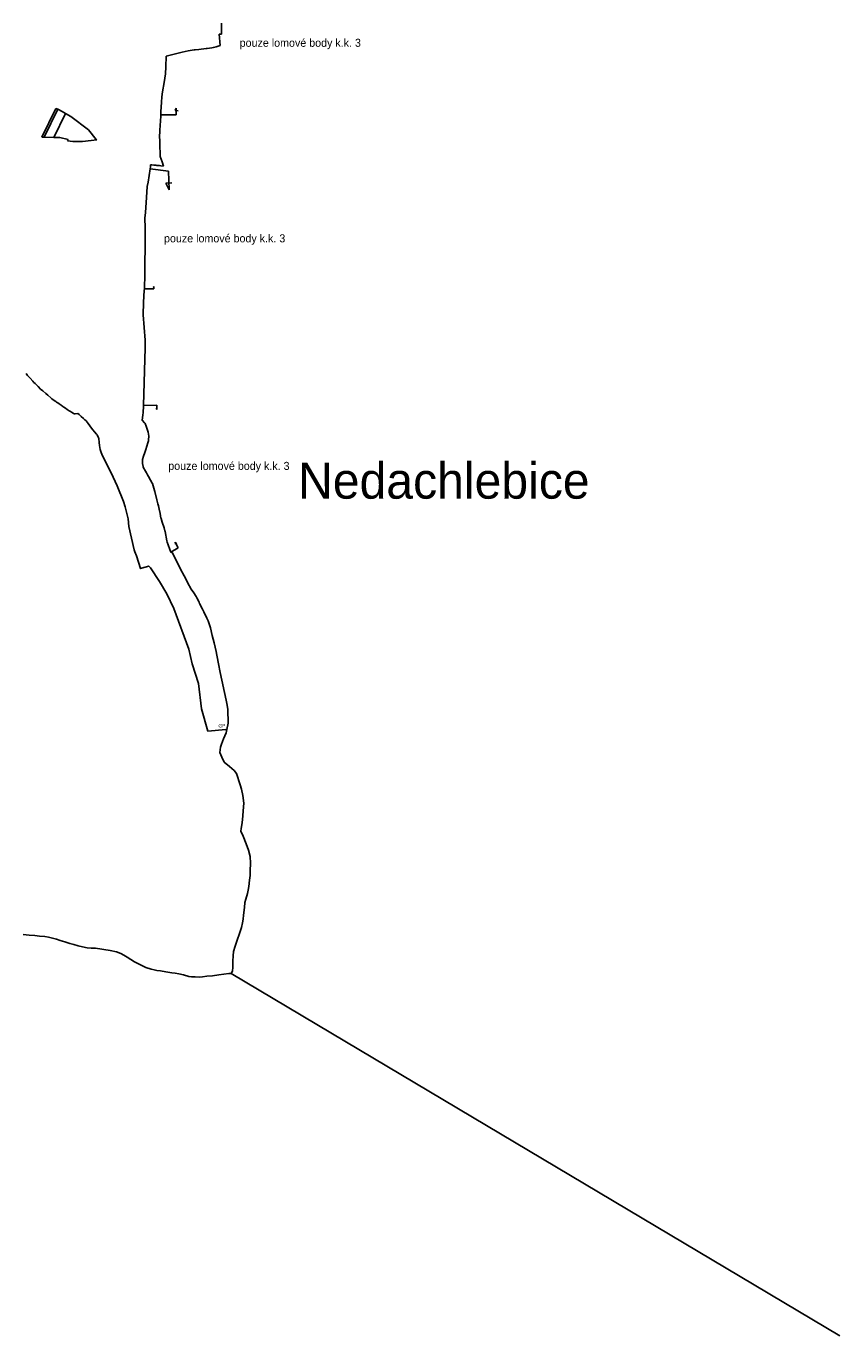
# Model space of a CAD drawing. Extents: x -534397 to -527742, y -1181460 to -1175250.
# Drawn here: x -530094 to -528058, y -1181460 to -1178187 of the extents above; entities that cross this region are included whole.
import ezdxf

# ---------------------------------------------------------------- set-up
doc = ezdxf.new("R2010")
doc.units = 0
for name, color, linetype in [('Hranice krajů', 7, 'Continuous'), ('Hranice obcí', 7, 'Continuous'), ('Hranice parcel', 7, 'Continuous'), ('Hranice státní', 7, 'Continuous')]:
    doc.layers.add(name, color=color, linetype=linetype)

msp = doc.modelspace()

# ---------------------------------------------------------------- linework, layer by layer
at = {"layer": 'Hranice obcí'}
for p, q in [((-530054.2, -1178464.1), (-530019.1, -1178392.1)), ((-530014.6, -1178394.3), (-530048.8, -1178464.3)), ((-530019.1, -1178392.1), (-530014.6, -1178394.3)), ((-530003.5, -1178399.7), (-530014.6, -1178394.3)), ((-530024.3, -1178465.1), (-529994.9, -1178404.8)), ((-529994.9, -1178404.8), (-530003.5, -1178399.7)), ((-529994.9, -1178404.8), (-529982.1, -1178412.4)), ((-529982.1, -1178412.4), (-529938.1, -1178445.4)), ((-529938.1, -1178445.4), (-529918.8, -1178469.8)), ((-530048.8, -1178464.3), (-530054.2, -1178464.1)), ((-530048.8, -1178464.3), (-530024.3, -1178465.1)), ((-530009.5, -1178464.6), (-530024.3, -1178465.1)), ((-529988.6, -1178469.9), (-530009.5, -1178464.6)), ((-529990.1, -1178473), (-529988.6, -1178469.9)), ((-529977.2, -1178475.2), (-529990.1, -1178473)), ((-529952.9, -1178475), (-529977.2, -1178475.2)), ((-529930.9, -1178472), (-529952.9, -1178475)), ((-529916.5, -1178470.8), (-529930.9, -1178472)), ((-529918.8, -1178469.8), (-529916.5, -1178470.8))]:
    msp.add_line(p, q, dxfattribs=at)
at = {"layer": 'Hranice parcel'}
for p, q in [((-529605, -1178178.9), (-529604.9, -1178206.2)), ((-529604.9, -1178206.2), (-529610.7, -1178206.2)), ((-529610.7, -1178206.2), (-529608.1, -1178234.8)), ((-529743.3, -1178261.9), (-529744.2, -1178287.8)), ((-529723.2, -1178256.8), (-529743.3, -1178261.9)), ((-529703.7, -1178251.8), (-529723.2, -1178256.8)), ((-529688.2, -1178247.9), (-529703.7, -1178251.8)), ((-529683.1, -1178247.2), (-529688.2, -1178247.9)), ((-529673.1, -1178245.9), (-529683.1, -1178247.2)), ((-529670.6, -1178245.6), (-529673.1, -1178245.9)), ((-529661.8, -1178244.7), (-529670.6, -1178245.6)), ((-529643.5, -1178242.7), (-529661.8, -1178244.7)), ((-529640.6, -1178242.4), (-529643.5, -1178242.7)), ((-529629, -1178240.6), (-529640.6, -1178242.4)), ((-529626.1, -1178239.9), (-529629, -1178240.6)), ((-529624.8, -1178239.6), (-529626.1, -1178239.9)), ((-529618.8, -1178238), (-529624.8, -1178239.6)), ((-529608.1, -1178234.8), (-529618.8, -1178238)), ((-529744.2, -1178287.8), (-529744.8, -1178305.4)), ((-529748.5, -1178327.5), (-529752.4, -1178350.3)), ((-529744.8, -1178305.4), (-529748.5, -1178327.5)), ((-529754.6, -1178363.3), (-529755.3, -1178376.8)), ((-529752.4, -1178350.3), (-529754.6, -1178363.3)), ((-529755.3, -1178376.8), (-529756.6, -1178400.5)), ((-529757.2, -1178411.3), (-529759, -1178446.3)), ((-529757, -1178407.8), (-529757.2, -1178411.3)), ((-529756.9, -1178406.4), (-529757, -1178407.8)), ((-529756.8, -1178403.5), (-529756.9, -1178406.4)), ((-529756.6, -1178400.5), (-529756.8, -1178403.5)), ((-529759.2, -1178450.2), (-529759.9, -1178462.5)), ((-529759.9, -1178462.5), (-529759.8, -1178465.5)), ((-529759, -1178446.3), (-529759.2, -1178450.2)), ((-529759.8, -1178465.5), (-529759.6, -1178469.4)), ((-529759.6, -1178469.4), (-529759.6, -1178470.8)), ((-529759.6, -1178470.8), (-529759.5, -1178475.1)), ((-529759.5, -1178475.1), (-529759.4, -1178478.6)), ((-529759.4, -1178478.6), (-529758.5, -1178512.6)), ((-529758.5, -1178512.6), (-529753.8, -1178525.7)), ((-529753.8, -1178525.7), (-529750.1, -1178536.2)), ((-529783.5, -1178543.1), (-529788.8, -1178576.5)), ((-529782.9, -1178538.2), (-529783.5, -1178543.1)), ((-529782.4, -1178533.3), (-529782.9, -1178538.2)), ((-529779.5, -1178533.5), (-529782.4, -1178533.3)), ((-529774.3, -1178533.9), (-529779.5, -1178533.5)), ((-529771.4, -1178534.1), (-529774.3, -1178533.9)), ((-529769, -1178534.3), (-529771.4, -1178534.1)), ((-529766.9, -1178534.4), (-529769, -1178534.3)), ((-529760, -1178535), (-529766.9, -1178534.4)), ((-529757.1, -1178535.3), (-529760, -1178535)), ((-529750.1, -1178536.2), (-529757.1, -1178535.3)), ((-529790.6, -1178587.4), (-529792.6, -1178614.4)), ((-529788.8, -1178576.5), (-529790.6, -1178587.4)), ((-529792.6, -1178614.4), (-529795.4, -1178652.2)), ((-529795.4, -1178652.2), (-529796.5, -1178666.3)), ((-529796.5, -1178666.3), (-529796.4, -1178690.8)), ((-529796.4, -1178690.8), (-529796.2, -1178750.8)), ((-529796.2, -1178750.8), (-529796.5, -1178767.8)), ((-529796.5, -1178767.8), (-529797.2, -1178806.5)), ((-529797.2, -1178806.5), (-529797.9, -1178843.3)), ((-529798.1, -1178846.2), (-529800.3, -1178877.4)), ((-529797.9, -1178843.3), (-529798.1, -1178846.2)), ((-529800.3, -1178877.4), (-529800.8, -1178908)), ((-529800.8, -1178908), (-529795.9, -1178971.7)), ((-529795.9, -1178971.7), (-529795.7, -1178990.6)), ((-529795.7, -1178990.6), (-529800.2, -1179134.3)), ((-529800.1, -1179136.6), (-529801.4, -1179151.9)), ((-529800.2, -1179134.3), (-529800.1, -1179136.6)), ((-529802, -1179158.7), (-529803.1, -1179171.3)), ((-529803.1, -1179171.3), (-529797.3, -1179177.5)), ((-529801.4, -1179151.9), (-529802, -1179158.7)), ((-529797.3, -1179177.5), (-529795.8, -1179179.2)), ((-529795.8, -1179179.2), (-529793.5, -1179185.8)), ((-529793.5, -1179185.8), (-529792.6, -1179188.5)), ((-529792.6, -1179188.5), (-529790.8, -1179193.7)), ((-529790.8, -1179193.7), (-529788.3, -1179201.2)), ((-529788.3, -1179201.2), (-529787.1, -1179211.3)), ((-529787.1, -1179211.9), (-529787.4, -1179219.4)), ((-529787.1, -1179211.3), (-529787.1, -1179211.9)), ((-529794.5, -1179244.2), (-529797.2, -1179252.1)), ((-529791.8, -1179236), (-529794.5, -1179244.2)), ((-529789.1, -1179227.8), (-529791.8, -1179236)), ((-529787.5, -1179223), (-529789.1, -1179227.8)), ((-529787.4, -1179219.4), (-529787.5, -1179223)), ((-529800.1, -1179260.9), (-529802.8, -1179269.2)), ((-529802.8, -1179269.2), (-529802.4, -1179279.2)), ((-529802.4, -1179279.2), (-529801, -1179286.9)), ((-529797.2, -1179252.1), (-529800.1, -1179260.9)), ((-529801, -1179286.9), (-529800.7, -1179288.5)), ((-529800.7, -1179288.5), (-529798.9, -1179292.8)), ((-529798.9, -1179292.8), (-529798, -1179294.3)), ((-529798, -1179294.3), (-529792.9, -1179303.1)), ((-529792.9, -1179303.1), (-529790.2, -1179307.7)), ((-529790.2, -1179307.7), (-529787.5, -1179312.2)), ((-529787.5, -1179312.2), (-529782.6, -1179320.8)), ((-529782.6, -1179320.8), (-529778.1, -1179328.5)), ((-529778.1, -1179328.5), (-529777.7, -1179329.9)), ((-529777.7, -1179329.9), (-529774.1, -1179341.4)), ((-529774.1, -1179341.4), (-529772.3, -1179347.4)), ((-529772.3, -1179347.4), (-529771.7, -1179349.7)), ((-529771.7, -1179349.7), (-529766.6, -1179370.4)), ((-529766.6, -1179370.4), (-529764, -1179380.7)), ((-529764, -1179380.7), (-529763, -1179385)), ((-529763, -1179385), (-529761.2, -1179393.4)), ((-529761.2, -1179393.4), (-529758.8, -1179404.8)), ((-529758.8, -1179404.8), (-529756.5, -1179416)), ((-529756.5, -1179416), (-529756.2, -1179417.1)), ((-529756.2, -1179417.1), (-529753.1, -1179426.5)), ((-529753.1, -1179426.5), (-529748.6, -1179440.1)), ((-529748.6, -1179440.1), (-529746.5, -1179448)), ((-529746.5, -1179448), (-529746, -1179449.8)), ((-529746, -1179449.8), (-529741.4, -1179472.6)), ((-529741.4, -1179472.6), (-529740.6, -1179476.5)), ((-529740.6, -1179476.5), (-529738.4, -1179482.6)), ((-529738.4, -1179482.6), (-529734.2, -1179494.4)), ((-529734.2, -1179494.4), (-529731.8, -1179501)), ((-529731.8, -1179501), (-529727.7, -1179503)), ((-529727.7, -1179503), (-529707.8, -1179543.3)), ((-529707.8, -1179543.3), (-529698.8, -1179560.3)), ((-529698.8, -1179560.3), (-529693.8, -1179569.6)), ((-529693.8, -1179569.6), (-529689.9, -1179576.9)), ((-529689.9, -1179576.9), (-529680.8, -1179593.5)), ((-529680.8, -1179593.5), (-529674.5, -1179602.8)), ((-529674.5, -1179602.8), (-529668.2, -1179612.1)), ((-529668.2, -1179612.1), (-529666.7, -1179615.2)), ((-529666.7, -1179615.2), (-529661.3, -1179625.8)), ((-529661.3, -1179625.8), (-529659.7, -1179629)), ((-529659.7, -1179629), (-529652.2, -1179643.7)), ((-529652.2, -1179643.7), (-529649.4, -1179649.9)), ((-529649.4, -1179649.9), (-529642.1, -1179665.7)), ((-529642.1, -1179665.7), (-529638.8, -1179672.9)), ((-529638.8, -1179672.9), (-529633.6, -1179687.5)), ((-529633.6, -1179687.5), (-529632.6, -1179690.4)), ((-529632.6, -1179690.4), (-529628.1, -1179709.5)), ((-529628.1, -1179709.5), (-529623.8, -1179727.9)), ((-529623.8, -1179727.9), (-529618.7, -1179749.7)), ((-529618.7, -1179749.7), (-529616.8, -1179758.3)), ((-529616.8, -1179758.3), (-529615.9, -1179762.6)), ((-529615.9, -1179762.6), (-529612.5, -1179779.8)), ((-529612.5, -1179779.8), (-529608.2, -1179801.8)), ((-529608.2, -1179801.8), (-529593.2, -1179870.8)), ((-529593.2, -1179870.8), (-529590.7, -1179883.2)), ((-529590.7, -1179883.2), (-529589.3, -1179894.2)), ((-529589.3, -1179894.2), (-529588.8, -1179928.1)), ((-529588.8, -1179928.1), (-529592, -1179944.2)), ((-529600.2, -1179968), (-529604.8, -1179980.7)), ((-529593.6, -1179952.7), (-529600.2, -1179968)), ((-529592, -1179944.2), (-529593.6, -1179952.7)), ((-529607.7, -1179988.8), (-529609.4, -1180001.9)), ((-529609.4, -1180001.9), (-529604.1, -1180013.2)), ((-529604.8, -1179980.7), (-529607.7, -1179988.8)), ((-529604.1, -1180013.2), (-529598.3, -1180025.7)), ((-529598.3, -1180025.7), (-529585.2, -1180036.6)), ((-529585.2, -1180036.6), (-529579, -1180041.6)), ((-529579, -1180041.6), (-529573.6, -1180046.8)), ((-529573.6, -1180046.8), (-529567.7, -1180054)), ((-529567.7, -1180054), (-529558.5, -1180082.4)), ((-529558.5, -1180082.4), (-529555.4, -1180093.5)), ((-529555.4, -1180093.5), (-529551.9, -1180109.4)), ((-529551.9, -1180109.4), (-529549.4, -1180128.1)), ((-529549.4, -1180128.1), (-529550.7, -1180147.6)), ((-529551.7, -1180160.4), (-529553.5, -1180177.4)), ((-529550.7, -1180147.6), (-529551.7, -1180160.4)), ((-529555.8, -1180191.9), (-529556.3, -1180198.2)), ((-529556.3, -1180198.2), (-529551.2, -1180211.2)), ((-529553.5, -1180177.4), (-529555.8, -1180191.9)), ((-529551.2, -1180211.2), (-529543.4, -1180229.9)), ((-529543.4, -1180229.9), (-529537.8, -1180245.8)), ((-529537.8, -1180245.8), (-529533.3, -1180261.7)), ((-529533.3, -1180261.7), (-529532.3, -1180278.5)), ((-529532.3, -1180278.5), (-529533.1, -1180297.5)), ((-529534.7, -1180321.1), (-529536.4, -1180337)), ((-529533.4, -1180308.9), (-529534.7, -1180321.1)), ((-529533.1, -1180297.5), (-529533.4, -1180308.9)), ((-529540.1, -1180353.9), (-529543.8, -1180367.9)), ((-529538.4, -1180346), (-529540.1, -1180353.9)), ((-529536.4, -1180337), (-529538.4, -1180346)), ((-529547.7, -1180388.8), (-529549.9, -1180408.3)), ((-529546.5, -1180377), (-529547.7, -1180388.8)), ((-529543.8, -1180367.9), (-529546.5, -1180377)), ((-529551.2, -1180418.6), (-529552.8, -1180427.7)), ((-529549.9, -1180408.3), (-529551.2, -1180418.6)), ((-530086.4, -1180458.4), (-530100.9, -1180456.8)), ((-530072.3, -1180459.4), (-530086.4, -1180458.4)), ((-530060.4, -1180460.4), (-530072.3, -1180459.4)), ((-529560.4, -1180454.2), (-529566.1, -1180470.8)), ((-529555.2, -1180438.7), (-529560.4, -1180454.2)), ((-529552.8, -1180427.7), (-529555.2, -1180438.7)), ((-530046.8, -1180461.5), (-530060.4, -1180460.4)), ((-530037.9, -1180463.6), (-530046.8, -1180461.5)), ((-530031.4, -1180465.1), (-530037.9, -1180463.6)), ((-530017.9, -1180468.6), (-530031.4, -1180465.1)), ((-530008.8, -1180471.2), (-530017.9, -1180468.6)), ((-529997, -1180475.1), (-530008.8, -1180471.2)), ((-529984.4, -1180479), (-529997, -1180475.1)), ((-529974.3, -1180481.8), (-529984.4, -1180479)), ((-529963.5, -1180485), (-529974.3, -1180481.8)), ((-529952.7, -1180487.8), (-529963.5, -1180485)), ((-529941.2, -1180490), (-529952.7, -1180487.8)), ((-529930.8, -1180490.9), (-529941.2, -1180490)), ((-529920.2, -1180491), (-529930.8, -1180490.9)), ((-529883.2, -1180496.9), (-529920.2, -1180491)), ((-529570.9, -1180485.7), (-529575.4, -1180498.9)), ((-529566.1, -1180470.8), (-529570.9, -1180485.7)), ((-529867.9, -1180500.2), (-529883.2, -1180496.9)), ((-529857.1, -1180503.9), (-529867.9, -1180500.2)), ((-529849.4, -1180507.9), (-529857.1, -1180503.9)), ((-529841.4, -1180512.9), (-529849.4, -1180507.9)), ((-529831.5, -1180518.8), (-529841.4, -1180512.9)), ((-529822.5, -1180524.5), (-529831.5, -1180518.8)), ((-529809.5, -1180531.9), (-529822.5, -1180524.5)), ((-529576.4, -1180523.5), (-529576.8, -1180539.3)), ((-529575.7, -1180510.3), (-529576.4, -1180523.5)), ((-529575.4, -1180498.9), (-529575.7, -1180510.3)), ((-529794.7, -1180538.9), (-529809.5, -1180531.9)), ((-529780.9, -1180543.3), (-529794.7, -1180538.9)), ((-529773.4, -1180545.2), (-529780.9, -1180543.3)), ((-529766.5, -1180546.4), (-529773.4, -1180545.2)), ((-529757.9, -1180547.7), (-529766.5, -1180546.4)), ((-529743.9, -1180550.2), (-529757.9, -1180547.7)), ((-529729.2, -1180552.5), (-529743.9, -1180550.2)), ((-529720.7, -1180553.3), (-529729.2, -1180552.5)), ((-529711.9, -1180555.3), (-529720.7, -1180553.3)), ((-529700.5, -1180557.8), (-529711.9, -1180555.3)), ((-529686.7, -1180561.3), (-529700.5, -1180557.8)), ((-529611.4, -1180557.5), (-529627.2, -1180559.8)), ((-529598.9, -1180556), (-529611.4, -1180557.5)), ((-529586.8, -1180554.2), (-529598.9, -1180556)), ((-529580.9, -1180554.3), (-529586.8, -1180554.2)), ((-529580.3, -1180553), (-529580.9, -1180554.3)), ((-529577.5, -1180547.6), (-529580.3, -1180553)), ((-529576.8, -1180539.3), (-529577.5, -1180547.6)), ((-529679.8, -1180562.1), (-529686.7, -1180561.3)), ((-529671.2, -1180562.8), (-529679.8, -1180562.1)), ((-529659.9, -1180563.2), (-529671.2, -1180562.8)), ((-529652.4, -1180562.3), (-529659.9, -1180563.2)), ((-529642, -1180561.1), (-529652.4, -1180562.3)), ((-529627.2, -1180559.8), (-529642, -1180561.1))]:
    msp.add_line(p, q, dxfattribs=at)
msp.add_lwpolyline([(-530094, -1179055), (-530090, -1179059.3), (-530087.7, -1179061.9), (-530083.8, -1179066.1), (-530077.1, -1179073.4), (-530074.1, -1179076.7), (-530071.3, -1179079.5), (-530067.2, -1179083.8), (-530063.7, -1179087.5), (-530058.1, -1179093.4), (-530052.1, -1179098.3), (-530044.3, -1179104.7), (-530039.7, -1179108.8), (-530032.2, -1179115.3), (-530029.1, -1179117.8), (-530025.9, -1179120.4), (-530019.6, -1179124.8), (-530017.8, -1179126), (-530014.8, -1179128.1), (-530011.5, -1179130.3), (-530006.3, -1179134), (-530002.1, -1179136.9), (-529999.2, -1179138.9), (-529995.3, -1179141.6), (-529991.3, -1179144.2), (-529986.1, -1179147.5), (-529982.9, -1179149.5), (-529980.1, -1179151.3), (-529978.6, -1179152.3), (-529975.4, -1179154.3), (-529973, -1179155.8), (-529971.1, -1179155.6), (-529964.4, -1179154.6), (-529961.3, -1179157.2), (-529958.4, -1179159.8), (-529956, -1179161.9), (-529950.5, -1179166.8), (-529946.7, -1179170.1), (-529943.5, -1179172.9), (-529941.2, -1179176.2), (-529938.9, -1179179.4), (-529930.6, -1179191.5), (-529927.3, -1179195), (-529922.8, -1179200.1), (-529917.7, -1179205.8), (-529915.8, -1179207.8), (-529912.8, -1179215), (-529911.7, -1179217.4), (-529910.7, -1179227), (-529909.9, -1179234.9), (-529909.1, -1179239.5), (-529908.3, -1179244.6), (-529906.5, -1179249.4), (-529903.3, -1179258.4), (-529903.2, -1179258.7), (-529899.3, -1179266.3), (-529896.6, -1179271.7), (-529881.2, -1179302.7), (-529866.1, -1179335.4), (-529850.4, -1179374.6), (-529845.8, -1179387.4), (-529838.5, -1179418.1), (-529836.6, -1179436.9), (-529823.5, -1179495.6), (-529821.9, -1179500.3), (-529817.5, -1179510.4), (-529807.6, -1179542.2), (-529805.3, -1179541.4), (-529787, -1179535.7), (-529782.8, -1179540.1), (-529760.1, -1179574.2), (-529742.2, -1179605.6), (-529724, -1179641.9), (-529687, -1179743.6), (-529678.2, -1179780.5), (-529662.8, -1179829), (-529654.9, -1179892.4), (-529639.1, -1179948.1), (-529594, -1179944.4), (-529592, -1179944.2)], dxfattribs=at)
at = {"layer": 'Hranice státní'}
for p, q in [((-529718.1, -1178391.1), (-529721.1, -1178397.1)), ((-529721.1, -1178397.1), (-529713.5, -1178397.8)), ((-529718.7, -1178408.2), (-529718.1, -1178391.1)), ((-529757, -1178407.8), (-529718.7, -1178408.2)), ((-529783.5, -1178543.1), (-529737.4, -1178548.7)), ((-529737.4, -1178548.7), (-529735.7, -1178595.2)), ((-529743.9, -1178578.9), (-529729.1, -1178578.1)), ((-529735.7, -1178595.2), (-529743.9, -1178578.9)), ((-529797.9, -1178843.3), (-529774.4, -1178842.6)), ((-529774.4, -1178836.9), (-529775.4, -1178839.3)), ((-529775.4, -1178839.3), (-529773.4, -1178839.3)), ((-529774.4, -1178842.6), (-529774.4, -1178836.9)), ((-529800.2, -1179134.3), (-529766.7, -1179133.6)), ((-529768.1, -1179141.2), (-529765, -1179141)), ((-529766.5, -1179144.9), (-529768.1, -1179141.2)), ((-529766.7, -1179133.6), (-529766.5, -1179144.9)), ((-529713.3, -1179490.6), (-529721.3, -1179476.5)), ((-529721.3, -1179476.5), (-529720.5, -1179481.4)), ((-529731.8, -1179501), (-529713.3, -1179490.6)), ((-529720.5, -1179481.4), (-529716.8, -1179479)), ((-529580.9, -1180554.3), (-528058.5, -1181459.5))]:
    msp.add_line(p, q, dxfattribs=at)

# ---------------------------------------------------------------- texts
at = {"layer": 'Hranice krajů'}
msp.add_text('Nedachlebice', height=90, dxfattribs=at).set_placement((-529413.6, -1179367.4))
at = {"layer": 'Hranice parcel'}
msp.add_text('GP', height=8.59, dxfattribs=at).set_placement((-529612.7, -1179939.2))
at = {"layer": 'Hranice státní'}
for p in [(-529559.6, -1178238.1), (-529748.8, -1178726.8), (-529738.2, -1179295.5)]:
    msp.add_text('pouze lomové body k.k. 3', height=20, dxfattribs=at).set_placement(p)

doc.saveas('drawing.dxf')
